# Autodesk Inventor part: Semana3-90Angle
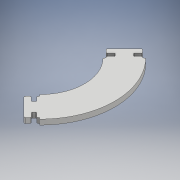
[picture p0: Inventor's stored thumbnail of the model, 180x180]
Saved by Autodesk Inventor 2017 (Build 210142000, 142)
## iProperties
Created: 2017-02
Part Number: Semana3-90Angle
Material: Generic
Document SubType Name: Modeling
Designer: diego
Density: 1 g/cm^3
Appearance: Default
d30: 7.500 mm
d31: 3.500 mm
d32: 15.000 mm
d33: 3.020 mm
d35: 3.000 mm
Author: diego
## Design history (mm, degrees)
node "Blocks"
  sketch "Block1"
    geometry: L1 (34.509, 30.759)-(34.509, 27.259); L2 (42.009, 30.759)-(42.009, 27.259); L3 (34.509, 27.259)-(30.759, 27.259); L4 (30.759, 27.259)-(30.759, 24.239); L5 (30.759, 24.239)-(45.759, 24.239); L6 (45.759, 24.239)-(45.759, 27.259); L7 (45.759, 27.259)-(42.009, 27.259); L8 (45.759, 30.759)-(45.759, 29.509); L9 (45.759, 29.509)-(30.759, 29.509); L10 (30.759, 29.509)-(30.759, 30.759); L11 (34.509, 30.759)-(42.009, 30.759); L12 (30.759, 30.759)-(45.759, 30.759); 1 further point
    constraints: 24 end point, 4 perpendicular, 3 collinear, 2 equal length, 2 horizontal, 2 vertical, 1 coincident, 1 parallel, 1 point on line
    dimensions: "d30" = 7.5 distance between parallel lines of L1 L2; "d31" = 3.5 distance of L1.start L1.end (computed from d35); "d32" = 15 distance of L4.end L5.end (= 2 x d30); "d33" = 3.02 distance between parallel lines of L3 L5 (computed from d35); "d34" = 1.25 distance of L9.end L10.end
sketch "Sketch2"
  geometry: L1 (0, 0)-(30.759, 30.759); L2 (0, 0)-(30.759, -30.759); L3 (-8.7, 0)-(52.2, 0) reference; L4 (18.385, 18.385)-(30.759, 30.759); L5 (19.962, 29.182)-(24.572, 24.572); L6 (18.385, -18.385)-(30.759, -30.759); A1 r 26 centre (0, 0) between (18.385, -18.385) and (18.385, 18.385); A2 r 43.5 centre (0, 0) between (30.759, -30.759) and (30.759, 30.759); 1 further point
  constraints: 10 end point, 4 point on circle, 2 centre point, 2 coincident, 2 collinear, 2 point on line, 1 horizontal, 1 midpoint, 1 perpendicular, 3 other
  dimensions: "d26" = 52 diameter of A1; "d27" = 87 diameter of A2; "d28" = 90 deg angle of L2 L1; "d29" = 45 deg angle of L3 L1
extrude "Extrusion1" new body sketch "Sketch2" stored distance "d38" = 3; taper "d39" = 0 deg
fillet "Fillet1" dims "d40" = 0.5
body "Solid1"
node "Block1:1" dims "d26" = 52, "d27" = 87, "d28" = 90 deg, "d29" = 45 deg
node "Block1:2" dims "d26" = 52, "d27" = 87, "d28" = 90 deg, "d29" = 45 deg
other parameters: "d35" = 3
